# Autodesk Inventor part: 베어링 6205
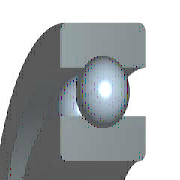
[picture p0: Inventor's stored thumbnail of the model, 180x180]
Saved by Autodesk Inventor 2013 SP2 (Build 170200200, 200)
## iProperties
Created: 2015-10
Part Number: 베어링 6205
Material: 강, 연강
Description: 깊은 그루브 볼 베어링
Document SubType Name: Modeling
Standard: KS B 2023
Designer: mdu
Standards Organization: KS
Language: ko-KR
Size Designation: 6205 - 25 x 52 x 15
Categories: <MemberInstance><Categories><Category DisplayName="샤프트 부품" InternalName="7f7aeb1f-a693-4053-b835-cee3144e0d98" Mnemonic="SHFT"><Category DisplayName="베어링" Inter
Density: 7.86 g/cm^3
Mass: 129.543 g
Surface Area: 107.326 cm^2
Volume: 16.4813 cm^3
IsCustomPart: 1
Author: mdu
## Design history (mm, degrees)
sketch "스케치" dims "d0" = 7.02 (= -0.26 x WD + 0.26 x BD)
  geometry: L1 (3.99, 19.25)-(11.01, 19.25); L2 (7.5, 19.25)-(7.5, 15.74); L3 (7.5, 19.25)-(7.5, 22.76); L4 (4.892, 16.901)-(0, 16.901); L5 (0, 12.5)-(15, 12.5); L6 (4.892, 21.599)-(0, 21.599); L7 (0, 26)-(15, 26); L8 (15, 12.5)-(15, 16.901); L9 (10.108, 16.901)-(15, 16.901); L10 (10.108, 21.599)-(15, 21.599); L11 (15, 26)-(15, 21.599); L12 (-1.4, 0)-(8.4, 0) reference; L13 (0, -0.3)-(0, 5.3) reference
  constraints: 22 end point, 4 point on line, 2 collinear, 2 perpendicular, 2 symmetric about line, 1 midpoint, 1 parallel, 14 other
  dimensions: "d9" = 25 diameter of L5 L12 (= WD); "d11" = 52 diameter of L7 L12 (= BD); "d12" = 15 distance between parallel lines of L8 L13 (= KB); "d13" = 33.802 diameter of L9 L12 (= 0.326 x BD + 0.674 x WD)
revolve "본체" stored, may be unused: angle "d6" = 90 deg
revolve "볼" stored, may be unused: angle "d7" = 90 deg
pattern_circular "IDS_ARRAYBALL[SIMPL:T]" dims angle "d3" = 360 deg
body "Solid1"
fillet "모깎기1" dims "d1" = 1 (= KRS)
other parameters: "WD" = 25 [user parameter; used in 5 equation terms], "BD" = 52 [user parameter; used in 5 equation terms], "KB" = 15 [user parameter; used in 1 equation term], "KRS" = 1 [user parameter; used in 1 equation term], "d4" = 0, "d5" = 0, "d8" = 0, "d14" = 0, "d15" = 0, "BBA" = 0 [user parameter], "BC0" = 7800000 [user parameter], "BC" = 1.4e+07 [user parameter], "BR" = 26 (= 0.5 x BD) [user parameter], "WR" = 12.5 (= 0.5 x WD) [user parameter]
